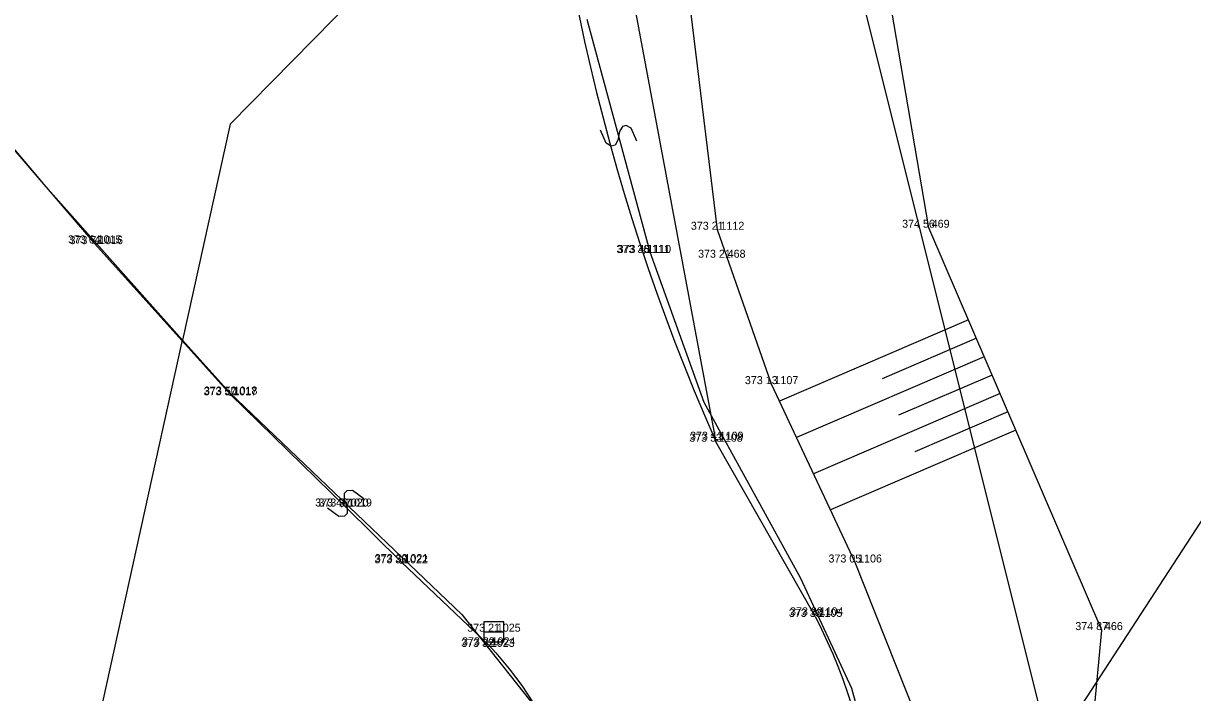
# Model space of a CAD drawing. Extents: x -601196 to -600262, y -1082523 to -1081922.
# Drawn here: x -600520.42 to -600491.19, y -1082194.29 to -1082177.56 of the extents above; entities that cross this region are included whole.
import ezdxf

# ---------------------------------------------------------------- set-up
doc = ezdxf.new("R2010")
doc.units = 0
for name, color, linetype in [('Vrstva 1', 7, 'Continuous'), ('Vrstva 10', 7, 'Continuous'), ('Vrstva 14', 7, 'Continuous'), ('Vrstva 2', 7, 'Continuous'), ('Vrstva 20', 7, 'Continuous'), ('Vrstva 25', 7, 'Continuous'), ('Vrstva 27', 7, 'Continuous'), ('Vrstva 3', 7, 'Continuous'), ('Vrstva 47', 7, 'Continuous')]:
    doc.layers.add(name, color=color, linetype=linetype)

msp = doc.modelspace()

# ---------------------------------------------------------------- linework, layer by layer
at = {"layer": 'Vrstva 1'}
for p, q in [((-600503.07, -1082182.72), (-600503.07, -1082182.72)), ((-600497.79, -1082182.67), (-600497.79, -1082182.67)), ((-600518.64, -1082183.06), (-600518.64, -1082183.06)), ((-600518.6, -1082183.08), (-600518.6, -1082183.08)), ((-600504.93, -1082183.3), (-600504.93, -1082183.3)), ((-600504.9, -1082183.3), (-600504.9, -1082183.3)), ((-600502.89, -1082183.42), (-600502.89, -1082183.42)), ((-600515.24, -1082186.84), (-600515.24, -1082186.84)), ((-600501.72, -1082186.58), (-600501.72, -1082186.58)), ((-600515.25, -1082186.86), (-600515.25, -1082186.86)), ((-600503.09, -1082187.97), (-600503.09, -1082187.97)), ((-600503.11, -1082188.02), (-600503.11, -1082188.02)), ((-600512.46, -1082189.64), (-600512.46, -1082189.64)), ((-600512.38, -1082189.64), (-600512.38, -1082189.64)), ((-600510.98, -1082191.06), (-600510.98, -1082191.06)), ((-600510.97, -1082191.03), (-600510.97, -1082191.03)), ((-600499.63, -1082191.04), (-600499.63, -1082191.04)), ((-600500.59, -1082192.36), (-600500.59, -1082192.36)), ((-600500.62, -1082192.4), (-600500.62, -1082192.4)), ((-600508.66, -1082192.77), (-600508.66, -1082192.77)), ((-600493.46, -1082192.73), (-600493.46, -1082192.73)), ((-600508.81, -1082193.15), (-600508.81, -1082193.15)), ((-600508.79, -1082193.11), (-600508.79, -1082193.11))]:
    msp.add_line(p, q, dxfattribs=at)
at = {"layer": 'Vrstva 10'}
for p, q in [((-600523.29, -1082177.66), (-600518.64, -1082183.06)), ((-600518.64, -1082183.06), (-600515.24, -1082186.84)), ((-600515.24, -1082186.84), (-600512.38, -1082189.64)), ((-600500.62, -1082192.4), (-600503.11, -1082188.02)), ((-600512.38, -1082189.64), (-600510.97, -1082191.03)), ((-600510.97, -1082191.03), (-600508.79, -1082193.11))]:
    msp.add_line(p, q, dxfattribs=at)
for points in [[(-600506.66, -1082176.73), (-600506.53, -1082177.372), (-600506.392, -1082178.012), (-600506.246, -1082178.651), (-600506.092, -1082179.287), (-600505.931, -1082179.922), (-600505.762, -1082180.555), (-600505.585, -1082181.185), (-600505.4, -1082181.814), (-600505.208, -1082182.44), (-600505.008, -1082183.063), (-600504.801, -1082183.685), (-600504.586, -1082184.303), (-600504.363, -1082184.919), (-600504.133, -1082185.532), (-600503.895, -1082186.143), (-600503.65, -1082186.75), (-600503.398, -1082187.354), (-600503.138, -1082187.956), (-600503.11, -1082188.02)], [(-600500.62, -1082192.4), (-600500.469, -1082192.704), (-600500.326, -1082193.012), (-600500.19, -1082193.323), (-600500.061, -1082193.636), (-600499.94, -1082193.953), (-600499.826, -1082194.273), (-600499.72, -1082194.595), (-600499.621, -1082194.92), (-600499.53, -1082195.247), (-600499.447, -1082195.576), (-600499.371, -1082195.907), (-600499.304, -1082196.239), (-600499.244, -1082196.574), (-600499.192, -1082196.909), (-600499.148, -1082197.245), (-600499.112, -1082197.583), (-600499.084, -1082197.921), (-600499.064, -1082198.26), (-600499.052, -1082198.599), (-600499.048, -1082198.938), (-600499.05, -1082199.18)], [(-600508.79, -1082193.11), (-600508.613, -1082193.3), (-600508.441, -1082193.496), (-600508.276, -1082193.697), (-600508.117, -1082193.903), (-600507.964, -1082194.114), (-600507.818, -1082194.329), (-600507.678, -1082194.549), (-600507.546, -1082194.772), (-600507.42, -1082195), (-600507.301, -1082195.232), (-600507.19, -1082195.467), (-600507.085, -1082195.705), (-600506.989, -1082195.946), (-600506.899, -1082196.191), (-600506.817, -1082196.438), (-600506.78, -1082196.56)]]:
    msp.add_lwpolyline(points, dxfattribs=at)
at = {"layer": 'Vrstva 14'}
for p, q in [((-600497.79, -1082182.67), (-600500.44, -1082167.05)), ((-600505.47, -1082175.38), (-600503.11, -1082188.02)), ((-600503.07, -1082182.72), (-600503.84, -1082176.4)), ((-600501.72, -1082186.58), (-600503.07, -1082182.72)), ((-600493.46, -1082192.73), (-600497.79, -1082182.67)), ((-600499.63, -1082191.04), (-600501.72, -1082186.58)), ((-600498.1, -1082194.9), (-600499.63, -1082191.04)), ((-600494.82, -1082206.84), (-600493.46, -1082192.73))]:
    msp.add_line(p, q, dxfattribs=at)
at = {"layer": 'Vrstva 20'}
for p, q in [((-600518.61, -1082183.08), (-600518.59, -1082183.08)), ((-600518.6, -1082183.065), (-600518.6, -1082183.08)), ((-600518.6, -1082183.095), (-600518.6, -1082183.08)), ((-600504.91, -1082183.3), (-600504.89, -1082183.3)), ((-600504.9, -1082183.285), (-600504.9, -1082183.3)), ((-600504.9, -1082183.315), (-600504.9, -1082183.3)), ((-600515.25, -1082186.845), (-600515.25, -1082186.86)), ((-600515.26, -1082186.86), (-600515.24, -1082186.86)), ((-600515.25, -1082186.875), (-600515.25, -1082186.86)), ((-600503.1, -1082187.97), (-600503.08, -1082187.97)), ((-600503.09, -1082187.955), (-600503.09, -1082187.97)), ((-600503.09, -1082187.985), (-600503.09, -1082187.97)), ((-600512.47, -1082189.64), (-600512.45, -1082189.64)), ((-600512.46, -1082189.625), (-600512.46, -1082189.64)), ((-600512.46, -1082189.655), (-600512.46, -1082189.64)), ((-600510.99, -1082191.06), (-600510.97, -1082191.06)), ((-600510.98, -1082191.045), (-600510.98, -1082191.06)), ((-600510.98, -1082191.075), (-600510.98, -1082191.06)), ((-600500.6, -1082192.36), (-600500.58, -1082192.36)), ((-600500.59, -1082192.345), (-600500.59, -1082192.36)), ((-600500.59, -1082192.375), (-600500.59, -1082192.36)), ((-600508.82, -1082193.15), (-600508.8, -1082193.15)), ((-600508.81, -1082193.135), (-600508.81, -1082193.15)), ((-600508.81, -1082193.165), (-600508.81, -1082193.15))]:
    msp.add_line(p, q, dxfattribs=at)
at = {"layer": 'Vrstva 25'}
for p, q in [((-600496.797, -1082184.976), (-600501.519, -1082187.009)), ((-600496.6, -1082185.435), (-600498.953, -1082186.448)), ((-600496.402, -1082185.894), (-600501.095, -1082187.914)), ((-600496.205, -1082186.353), (-600498.544, -1082187.36)), ((-600496.007, -1082186.813), (-600500.67, -1082188.82)), ((-600495.809, -1082187.272), (-600498.134, -1082188.272)), ((-600495.612, -1082187.731), (-600500.246, -1082189.725))]:
    msp.add_line(p, q, dxfattribs=at)
at = {"layer": 'Vrstva 27'}
msp.add_line((-600508.91, -1082192.77), (-600508.41, -1082192.77), dxfattribs=at)
msp.add_lwpolyline([(-600508.91, -1082193.02), (-600508.41, -1082193.02), (-600508.41, -1082192.52), (-600508.91, -1082192.52)], close=True, dxfattribs=at)
at = {"layer": 'Vrstva 47'}
for p, q in [((-600501.37, -1082169.29), (-600494.74, -1082195.8)), ((-600515.25, -1082180.08), (-600506.42, -1082171.1)), ((-600527.07, -1082173.12), (-600519.94, -1082181.55)), ((-600504.75, -1082183.28), (-600506.33, -1082177.46)), ((-600515.25, -1082180.08), (-600516.44, -1082185.48)), ((-600505.351, -1082180.111), (-600505.447, -1082180.137)), ((-600505.228, -1082180.181), (-600505.351, -1082180.111)), ((-600494.74, -1082195.8), (-600484.44, -1082179.95)), ((-600505.851, -1082180.558), (-600505.991, -1082180.233)), ((-600505.517, -1082180.26), (-600505.562, -1082180.479)), ((-600505.447, -1082180.137), (-600505.517, -1082180.26)), ((-600505.088, -1082180.506), (-600505.228, -1082180.181)), ((-600505.728, -1082180.628), (-600505.851, -1082180.558)), ((-600505.632, -1082180.602), (-600505.728, -1082180.628)), ((-600505.562, -1082180.479), (-600505.632, -1082180.602)), ((-600519.94, -1082181.55), (-600516.44, -1082185.48)), ((-600503.4, -1082187.04), (-600504.75, -1082183.28)), ((-600519.77, -1082200.58), (-600516.44, -1082185.48)), ((-600516.44, -1082185.48), (-600515.27, -1082186.79)), ((-600515.27, -1082186.79), (-600509.46, -1082192.34)), ((-600500.99, -1082191.44), (-600503.4, -1082187.04)), ((-600512.336, -1082189.246), (-600512.406, -1082189.318)), ((-600512.406, -1082189.318), (-600512.402, -1082189.459)), ((-600512.402, -1082189.459), (-600512.327, -1082189.67)), ((-600512.195, -1082189.242), (-600512.336, -1082189.246)), ((-600511.907, -1082189.448), (-600512.195, -1082189.242)), ((-600512.534, -1082189.887), (-600512.822, -1082189.681)), ((-600512.327, -1082189.67), (-600512.324, -1082189.811)), ((-600512.393, -1082189.883), (-600512.534, -1082189.887)), ((-600512.324, -1082189.811), (-600512.393, -1082189.883)), ((-600499.71, -1082194.19), (-600500.99, -1082191.44)), ((-600509.46, -1082192.34), (-600507.59, -1082194.71)), ((-600499.18, -1082196.13), (-600499.71, -1082194.19))]:
    msp.add_line(p, q, dxfattribs=at)

# ---------------------------------------------------------------- texts
at = {"layer": 'Vrstva 2'}
for s, p in [(' 1112', (-600503.07, -1082182.72)), (' 469', (-600497.79, -1082182.67)), (' 1015', (-600518.64, -1082183.06)), (' 1016', (-600518.6, -1082183.08)), (' 1111', (-600504.93, -1082183.3)), (' 1110', (-600504.9, -1082183.3)), (' 468', (-600502.89, -1082183.42)), (' 1107', (-600501.72, -1082186.58)), (' 1017', (-600515.25, -1082186.86)), (' 1018', (-600515.24, -1082186.84)), (' 1108', (-600503.11, -1082188.02)), (' 1109', (-600503.09, -1082187.97)), (' 1020', (-600512.46, -1082189.64)), (' 1019', (-600512.38, -1082189.64)), (' 1022', (-600510.98, -1082191.06)), (' 1021', (-600510.97, -1082191.03)), (' 1106', (-600499.63, -1082191.04)), (' 1105', (-600500.62, -1082192.4)), (' 1104', (-600500.59, -1082192.36)), (' 1025', (-600508.66, -1082192.77)), (' 466', (-600493.46, -1082192.73)), (' 1023', (-600508.81, -1082193.15)), (' 1024', (-600508.79, -1082193.11))]:
    msp.add_text(s, height=0.2, dxfattribs=at).set_placement(p)
at = {"layer": 'Vrstva 3'}
for s, p in [('373 21 ', (-600503.736, -1082182.72)), ('374 56 ', (-600498.456, -1082182.67)), ('373 64 ', (-600519.306, -1082183.06)), ('373 72 ', (-600519.266, -1082183.08)), ('373 36 ', (-600505.596, -1082183.3)), ('373 45 ', (-600505.566, -1082183.3)), ('373 21 ', (-600503.556, -1082183.42)), ('373 13 ', (-600502.386, -1082186.58)), ('373 57 ', (-600515.916, -1082186.86)), ('373 50 ', (-600515.906, -1082186.84)), ('373 33 ', (-600503.776, -1082188.02)), ('373 41 ', (-600503.756, -1082187.97)), ('373 46 ', (-600513.126, -1082189.64)), ('373 37 ', (-600513.046, -1082189.64)), ('373 36 ', (-600511.646, -1082191.06)), ('373 30 ', (-600511.636, -1082191.03)), ('373 05 ', (-600500.296, -1082191.04)), ('373 33 ', (-600501.286, -1082192.4)), ('373 39 ', (-600501.256, -1082192.36)), ('373 21 ', (-600509.326, -1082192.77)), ('374 87 ', (-600494.126, -1082192.73)), ('373 32 ', (-600509.476, -1082193.15)), ('373 22 ', (-600509.456, -1082193.11))]:
    msp.add_text(s, height=0.2, dxfattribs=at).set_placement(p)

doc.saveas('drawing.dxf')
